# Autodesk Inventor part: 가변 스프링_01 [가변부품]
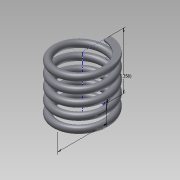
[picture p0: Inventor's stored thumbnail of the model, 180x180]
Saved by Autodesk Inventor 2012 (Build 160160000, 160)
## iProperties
Created: 2015-05
Part Number: 가변 스프링_01 [가변부품]
Material: 탄소강
Document SubType Name: Modeling
Designer: Administrator
Density: 7.87 g/cm^3
Mass: 18.7439 g
Surface Area: 32.4126 cm^2
Volume: 2.3817 cm^3
Author: Administrator
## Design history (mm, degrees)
sketch "스케치2"
  geometry: L1 (0, 0)-(11, 0); L2 (11, 0)-(11, 25.358); L3 (11, 25.358)-(0, 25.358); L4 (0, 25.358)-(0, 0); C1 r 1.5 at (11, 0)
  constraints: 8 end point, 2 parallel, 1 centre point, 1 coincident, 1 horizontal, 1 perpendicular
  dimensions: "d0" = 22 diameter of L2 L4; "d1" = 25.35829 distance of L1.end L2.end (derived); "d2" = 3 diameter of C1
feature "코일1" pitch "d3" = 10; turns "d5" = 5; dims "d4" = 25.35829 (= d1), "d6" = 0, angle "d7" = 90 deg, angle "d8" = 90 deg, "d9" = 0, "d10" = 0
sketch "스케치3"
  geometry: L1 (0, 12.5)-(0, 9.5) reference; 1 further point
  constraints: 1 vertical alignment
extrude "돌출1" cut sketch "스케치3" stored distance "d11" = 10; taper "d12" = 0 deg
node "작업 평면1"
sketch "스케치4"
  geometry: L1 (0, 12.5)-(0, 9.5) reference; 1 further point
  constraints: 1 vertical alignment
extrude "돌출2" cut sketch "스케치4" stored distance "d13" = 10; taper "d14" = 0 deg
node "솔리드1"
node "절단 모서리 투영1"
node "절단 모서리 투영2"
